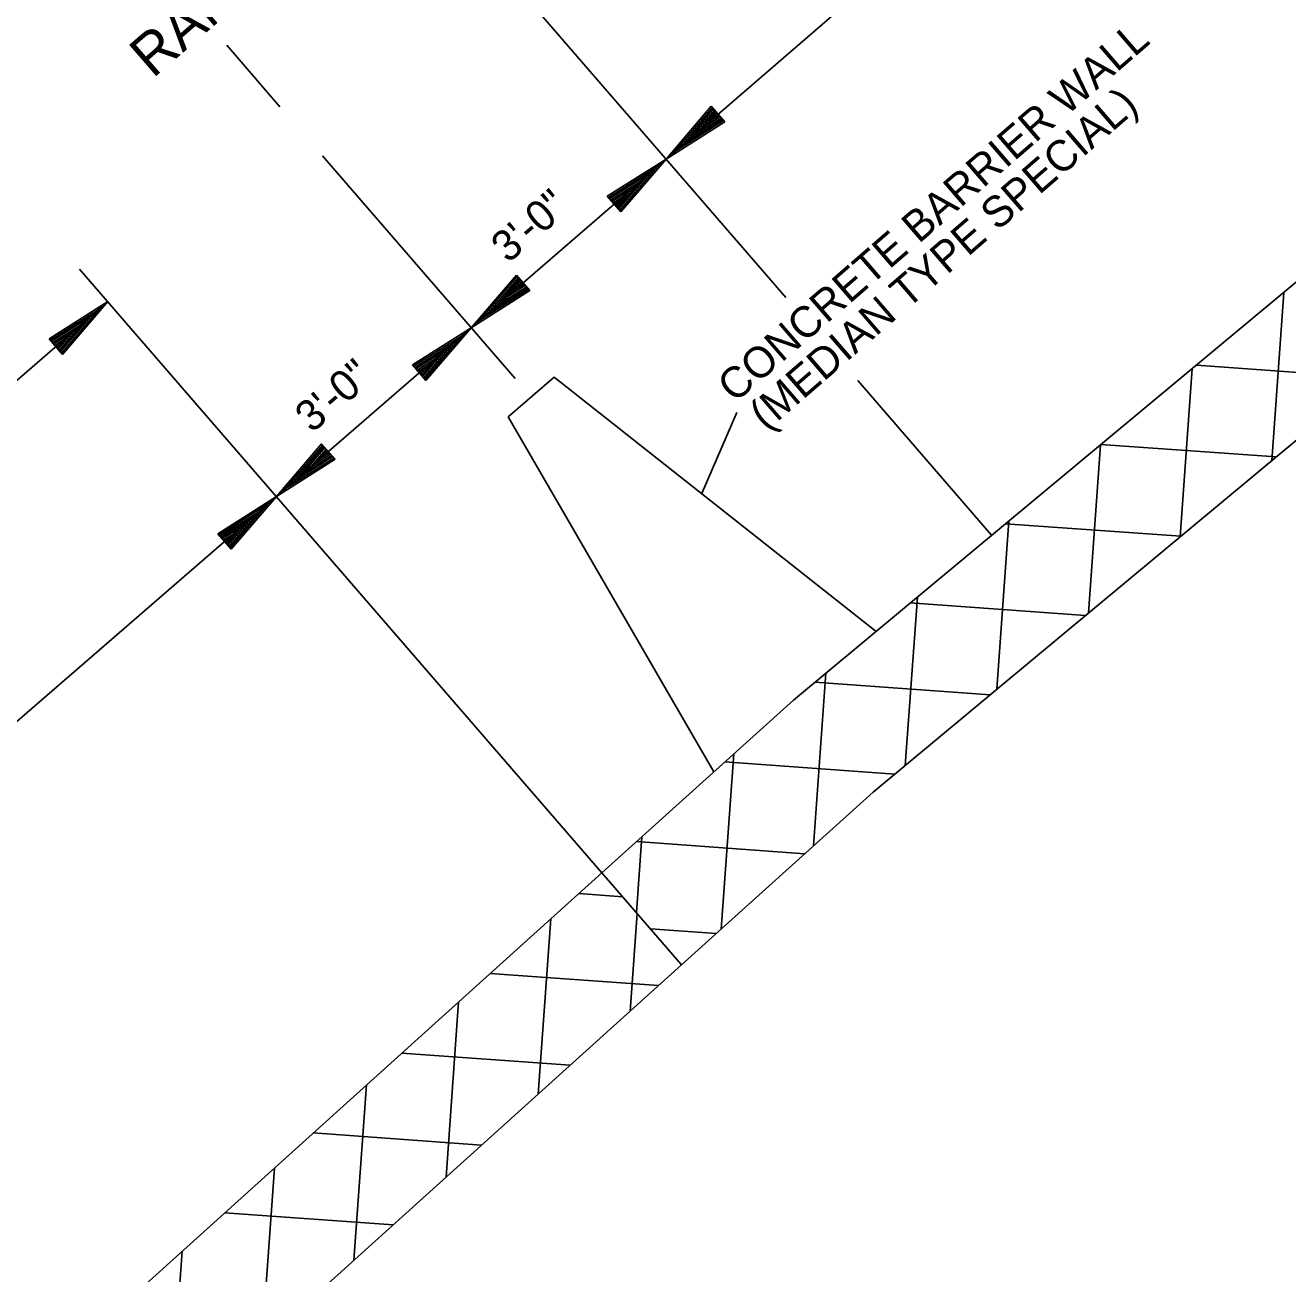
# Model space of a CAD drawing. Extents: x 192699 to 285914, y 194342 to 233219.
# Drawn here: x 262861.16 to 262875.86, y 213604.46 to 213618.99 of the extents above; entities that cross this region are included whole.
import ezdxf

# ---------------------------------------------------------------- set-up
doc = ezdxf.new("R2010")
doc.units = 0
doc.layers.add('TYPICAL SECTION FOR MOT', color=7, linetype='Continuous')

msp = doc.modelspace()

# ---------------------------------------------------------------- linework, layer by layer
at = {"layer": 'TYPICAL SECTION FOR MOT'}
for p, q in [((262868.62, 213617.43), (262879.96, 213627.248)), ((262870.103, 213611.134), (262883.947, 213622.643)), ((262871.03, 213610.063), (262884.875, 213621.572)), ((262870.014, 213615.819), (262866.329, 213620.076)), ((262864.125, 213618.039), (262863.505, 213618.755)), ((262869.146, 213618.045), (262868.62, 213617.43)), ((262869.159, 213618.03), (262868.721, 213617.518)), ((262869.172, 213618.014), (262868.825, 213617.608)), ((262869.186, 213617.999), (262868.925, 213617.695)), ((262869.199, 213617.984), (262869.028, 213617.784)), ((262869.25, 213617.925), (262869.028, 213617.784)), ((262869.212, 213617.968), (262869.129, 213617.871)), ((262869.237, 213617.94), (262869.129, 213617.871)), ((262869.303, 213617.863), (262869.146, 213618.045)), ((262869.303, 213617.863), (262868.62, 213617.43)), ((262869.29, 213617.878), (262868.721, 213617.518)), ((262869.277, 213617.894), (262868.825, 213617.608)), ((262869.264, 213617.909), (262868.925, 213617.695)), ((262866.864, 213614.875), (262864.619, 213617.468)), ((262866.352, 213615.467), (262868.62, 213617.43)), ((262867.936, 213616.997), (262868.62, 213617.43)), ((262867.949, 213616.982), (262868.519, 213617.343)), ((262868.08, 213616.831), (262868.519, 213617.343)), ((262868.093, 213616.816), (262868.62, 213617.43)), ((262867.963, 213616.967), (262868.415, 213617.253)), ((262868.067, 213616.847), (262868.415, 213617.253)), ((262867.976, 213616.952), (262868.314, 213617.166)), ((262867.99, 213616.936), (262868.211, 213617.077)), ((262868.041, 213616.877), (262868.211, 213617.077)), ((262868.054, 213616.862), (262868.314, 213617.166)), ((262867.936, 213616.997), (262868.093, 213616.816)), ((262868.003, 213616.921), (262868.11, 213616.989)), ((262868.027, 213616.892), (262868.11, 213616.989)), ((262867.874, 213609.125), (262861.793, 213616.149)), ((262866.878, 213616.081), (262866.352, 213615.467)), ((262866.891, 213616.066), (262866.453, 213615.554)), ((262866.904, 213616.051), (262866.557, 213615.644)), ((262866.917, 213616.035), (262866.657, 213615.731)), ((262866.931, 213616.02), (262866.76, 213615.82)), ((262866.944, 213616.005), (262866.861, 213615.908)), ((262867.035, 213615.9), (262866.878, 213616.081)), ((262867.035, 213615.9), (262866.352, 213615.467)), ((262867.022, 213615.915), (262866.453, 213615.554)), ((262867.009, 213615.93), (262866.557, 213615.644)), ((262866.995, 213615.945), (262866.657, 213615.731)), ((262866.982, 213615.961), (262866.76, 213615.82)), ((262866.969, 213615.976), (262866.861, 213615.908)), ((262875.67, 213613.92), (262875.811, 213615.879)), ((262846.243, 213602.026), (262862.12, 213615.771)), ((262861.437, 213615.338), (262862.12, 213615.771)), ((262861.594, 213615.157), (262862.12, 213615.771)), ((262861.45, 213615.323), (262862.019, 213615.684)), ((262861.463, 213615.308), (262861.915, 213615.594)), ((262861.567, 213615.188), (262861.915, 213615.594)), ((262861.581, 213615.172), (262862.019, 213615.684)), ((262861.476, 213615.293), (262861.814, 213615.507)), ((262861.49, 213615.277), (262861.712, 213615.418)), ((262861.541, 213615.218), (262861.712, 213615.418)), ((262861.554, 213615.203), (262861.814, 213615.507)), ((262864.083, 213613.503), (262866.352, 213615.467)), ((262865.668, 213615.034), (262866.352, 213615.467)), ((262865.825, 213614.852), (262866.352, 213615.467)), ((262861.437, 213615.338), (262861.594, 213615.157)), ((262861.503, 213615.262), (262861.611, 213615.33)), ((262861.527, 213615.233), (262861.611, 213615.33)), ((262865.681, 213615.019), (262866.251, 213615.379)), ((262865.695, 213615.003), (262866.147, 213615.289)), ((262865.799, 213614.883), (262866.147, 213615.289)), ((262865.812, 213614.868), (262866.251, 213615.379)), ((262865.708, 213614.988), (262866.046, 213615.202)), ((262865.786, 213614.898), (262866.046, 213615.202)), ((262865.668, 213615.034), (262865.825, 213614.852)), ((262865.721, 213614.972), (262865.943, 213615.113)), ((262865.734, 213614.957), (262865.842, 213615.026)), ((262865.759, 213614.929), (262865.842, 213615.026)), ((262865.772, 213614.913), (262865.943, 213615.113)), ((262874.604, 213613.034), (262874.745, 213614.993)), ((262874.793, 213615.033), (262876.832, 213614.886)), ((262866.781, 213614.43), (262867.316, 213614.894)), ((262867.316, 213614.894), (262871.064, 213611.933)), ((262872.41, 213613.052), (262870.852, 213614.852)), ((262866.781, 213614.43), (262869.174, 213610.297)), ((262869.445, 213614.48), (262869.032, 213613.53)), ((262864.61, 213614.118), (262864.083, 213613.503)), ((262864.623, 213614.102), (262864.184, 213613.591)), ((262864.767, 213613.936), (262864.61, 213614.118)), ((262873.538, 213612.147), (262873.679, 213614.106)), ((262873.683, 213614.11), (262875.722, 213613.963)), ((262864.754, 213613.951), (262864.184, 213613.591)), ((262864.636, 213614.087), (262864.289, 213613.681)), ((262864.74, 213613.967), (262864.289, 213613.681)), ((262864.649, 213614.072), (262864.389, 213613.768)), ((262864.727, 213613.982), (262864.389, 213613.768)), ((262864.663, 213614.056), (262864.492, 213613.857)), ((262864.714, 213613.997), (262864.492, 213613.857)), ((262864.676, 213614.041), (262864.593, 213613.944)), ((262864.701, 213614.013), (262864.593, 213613.944)), ((262864.767, 213613.936), (262864.083, 213613.503)), ((262852.743, 213603.685), (262864.083, 213613.503)), ((262863.4, 213613.07), (262864.083, 213613.503)), ((262863.413, 213613.055), (262863.982, 213613.416)), ((262863.544, 213612.904), (262863.982, 213613.416)), ((262863.557, 213612.889), (262864.083, 213613.503)), ((262863.427, 213613.04), (262863.878, 213613.326)), ((262863.44, 213613.025), (262863.778, 213613.239)), ((262863.518, 213612.935), (262863.778, 213613.239)), ((262863.531, 213612.919), (262863.878, 213613.326)), ((262872.471, 213611.261), (262872.612, 213613.22)), ((262863.4, 213613.07), (262863.557, 213612.889)), ((262863.453, 213613.009), (262863.675, 213613.15)), ((262863.504, 213612.95), (262863.675, 213613.15)), ((262872.573, 213613.187), (262874.612, 213613.041)), ((262863.466, 213612.994), (262863.574, 213613.062)), ((262863.491, 213612.965), (262863.574, 213613.062)), ((262871.405, 213610.374), (262871.546, 213612.333)), ((262871.463, 213612.265), (262873.502, 213612.118)), ((262870.335, 213609.436), (262870.479, 213611.447)), ((262870.353, 213611.342), (262872.392, 213611.195)), ((262870.103, 213611.134), (262867.874, 213609.125)), ((262869.263, 213608.469), (262869.409, 213610.508)), ((262869.305, 213610.415), (262871.283, 213610.272)), ((262871.03, 213610.063), (262868.801, 213608.054)), ((262868.274, 213608.663), (262868.337, 213609.542)), ((262868.275, 213609.486), (262870.234, 213609.345)), ((262867.874, 213609.125), (262856.73, 213599.08)), ((262867.874, 213609.125), (262868.801, 213608.054)), ((262867.604, 213608.881), (262868.117, 213608.844)), ((262867.13, 213606.547), (262867.277, 213608.586)), ((262868.202, 213607.513), (262868.284, 213608.651)), ((262868.439, 213608.472), (262869.204, 213608.417)), ((262868.801, 213608.054), (262857.657, 213598.009)), ((262866.573, 213607.952), (262868.533, 213607.811)), ((262866.058, 213605.581), (262866.204, 213607.62)), ((262865.543, 213607.024), (262867.502, 213606.883)), ((262864.986, 213604.614), (262865.132, 213606.654)), ((262864.513, 213606.096), (262866.472, 213605.955)), ((262863.913, 213603.648), (262864.06, 213605.687)), ((262863.483, 213605.167), (262865.442, 213605.026)), ((262862.841, 213602.682), (262862.988, 213604.721))]:
    msp.add_line(p, q, dxfattribs=at)

# ---------------------------------------------------------------- texts
for s, height, p in [('RAMP', 0.48, (262862.644, 213618.362)), ('CONCRETE BARRIER WALL', 0.36, (262869.418, 213614.583)), ('(MEDIAN TYPE SPECIAL)', 0.36, (262869.788, 213614.258)), ('3\'-0"', 0.36, (262866.781, 213616.209)), ('3\'-0"', 0.36, (262864.498, 213614.233))]:
    msp.add_text(s, height=height, rotation=40.8833, dxfattribs=at).set_placement(p)

doc.saveas('drawing.dxf')
